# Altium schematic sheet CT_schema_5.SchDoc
size 479 x 328 mm
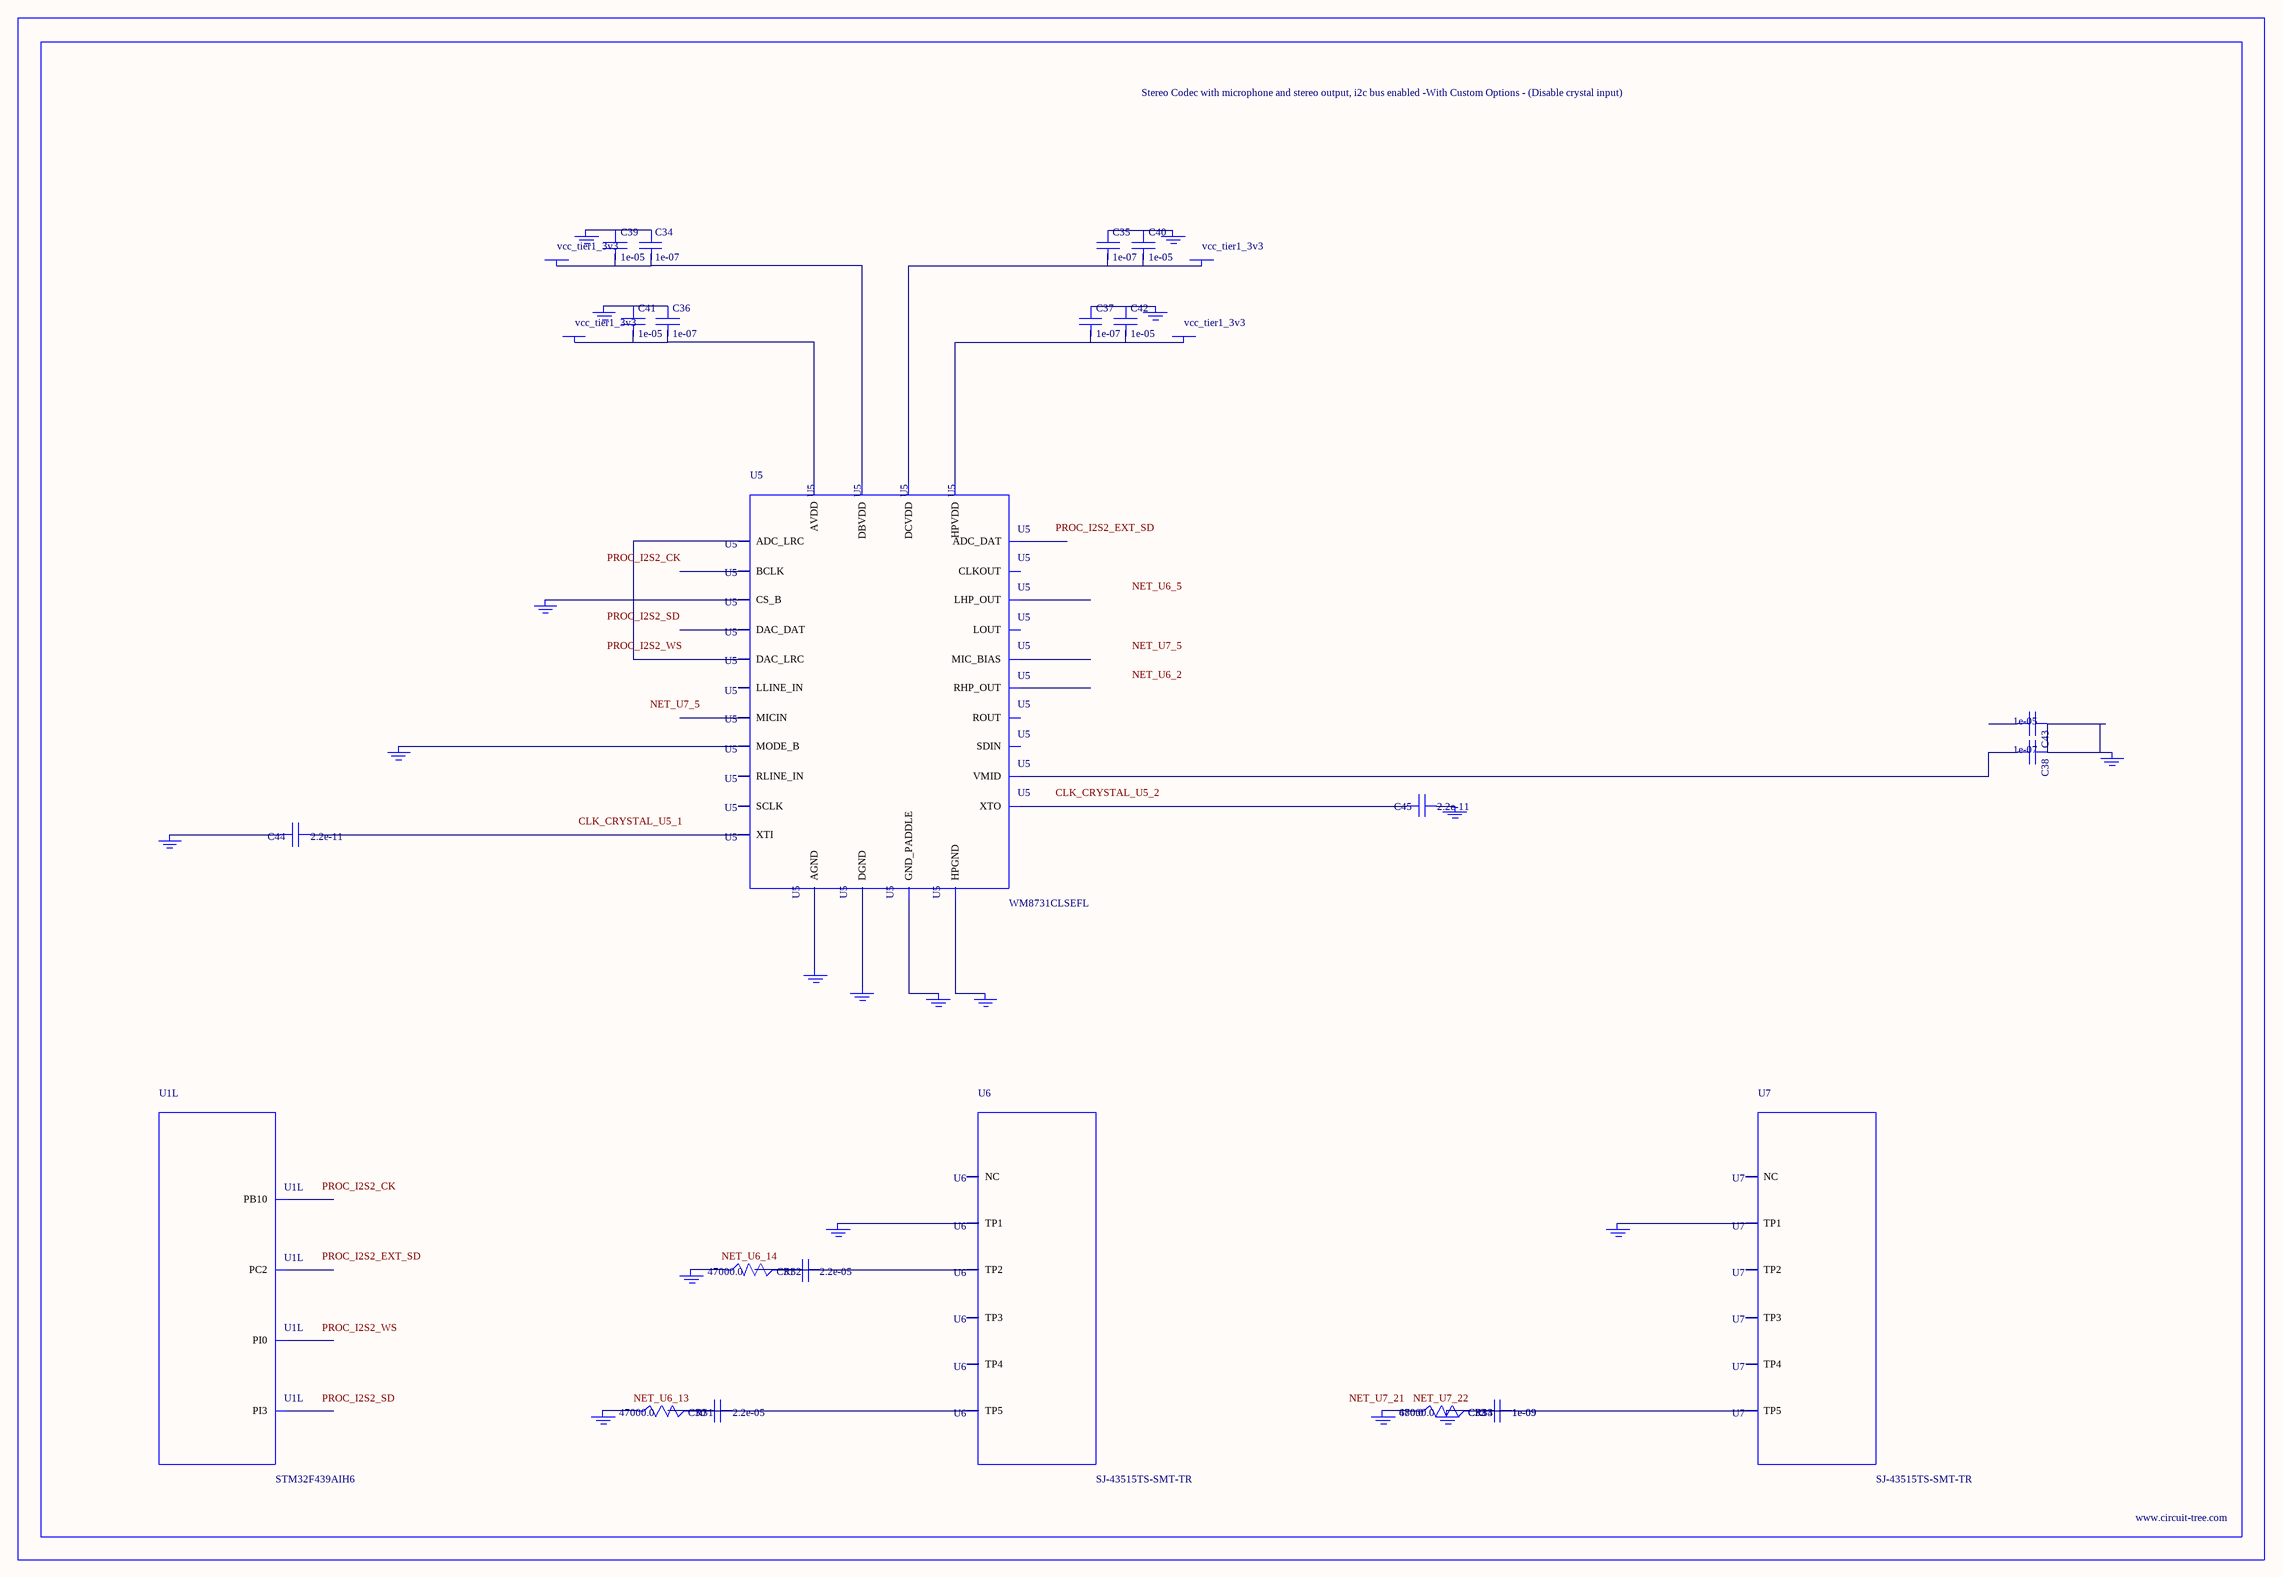
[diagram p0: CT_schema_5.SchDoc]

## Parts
BORDER4  (no value)
C30  2.2e-05  [C1210]
C31  2.2e-05  [C1210]
C32  1e-09  [C0402]
C33  1e-09  [C0402]
C34  1e-07  [C0402]
C35  1e-07  [C0402]
C36  1e-07  [C0402]
C37  1e-07  [C0402]
C38  1e-07  [C0402]
C39  1e-05  [C0805]
C40  1e-05  [C0805]
C41  1e-05  [C0805]
C42  1e-05  [C0805]
C43  1e-05  [C0805]
C44  2.2e-11  [C0402]
C45  2.2e-11  [C0402]
GND_INSTANCE_4_0  (no value)
GND_INSTANCE_4_1  (no value)
GND_INSTANCE_4_2  (no value)
GND_INSTANCE_4_3  (no value)
GND_INSTANCE_4_4  (no value)
GND_INSTANCE_4_5  (no value)
GND_INSTANCE_4_6  (no value)
GND_INSTANCE_4_7  (no value)
GND_INSTANCE_4_8  (no value)
GND_INSTANCE_4_9  (no value)
GND_INSTANCE_4_10  (no value)
GND_INSTANCE_4_11  (no value)
GND_INSTANCE_4_12  (no value)
GND_INSTANCE_4_13  (no value)
GND_INSTANCE_4_14  (no value)
GND_INSTANCE_4_15  (no value)
GND_INSTANCE_4_16  (no value)
GND_INSTANCE_4_17  (no value)
GND_INSTANCE_4_18  (no value)
POWER_INSTANCE_4_0  vcc_tier1_3v3
POWER_INSTANCE_4_1  vcc_tier1_3v3
POWER_INSTANCE_4_2  vcc_tier1_3v3
POWER_INSTANCE_4_3  vcc_tier1_3v3
R31  47000.0  [R0603]
R32  47000.0  [R0603]
R33  47000.0  [R0603]
R34  680.0  [R0603]
U1  STM32F439AIH6  [UFBGA169]  (part L of 12)
U5  WM8731CLSEFL  [QFN-28]
U6  SJ-43515TS-SMT-TR  [SJ-43515TS-SMT-TR]
U7  SJ-43515TS-SMT-TR  [SJ-43515TS-SMT-TR]

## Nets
NetC30_1: C30.1 C30.2 R31.2 U6.5(TP5)
NetC31_1: C31.1 C31.2 R32.2 U6.2(TP2)
NetC32_1: C32.1 C32.2 C33.1 C33.2 GND_INSTANCE_4_18.0(GND) R33.2 R34.2 U7.5(TP5)
NetC34_1: C34.1 C39.1 GND_INSTANCE_4_3.0(GND)
NetC34_2: C34.2 C39.2 POWER_INSTANCE_4_1.0(PWR) U5.5(DBVDD)
NetC35_1: C35.1 C40.1 GND_INSTANCE_4_2.0(GND)
NetC35_2: C35.2 C40.2 POWER_INSTANCE_4_0.0(PWR) U5.3(DCVDD)
NetC36_1: C36.1 C41.1 GND_INSTANCE_4_6.0(GND)
NetC36_2: C36.2 C41.2 POWER_INSTANCE_4_3.0(PWR) U5.18(AVDD)
NetC37_1: C37.1 C42.1 GND_INSTANCE_4_4.0(GND)
NetC37_2: C37.2 C42.2 POWER_INSTANCE_4_2.0(PWR) U5.12(HPVDD)
NetC38_1: C38.1 C43.1 GND_INSTANCE_4_7.0(GND)
NetC38_2: C38.2 U5.20(VMID)
NetC44_1: C44.1 U5.1(XTI)
NetC44_2: C44.2 GND_INSTANCE_4_0.0(GND)
NetC45_1: C45.1 GND_INSTANCE_4_1.0(GND)
NetC45_2: C45.2 U5.2(XTO)
NetGND_INSTANCE_4_5_0: GND_INSTANCE_4_5.0(GND) U5.15(HPGND)
NetGND_INSTANCE_4_8_0: GND_INSTANCE_4_8.0(GND) U5.25(MODE_B)
NetGND_INSTANCE_4_9_0: GND_INSTANCE_4_9.0(GND) U5.26(CS_B)
NetGND_INSTANCE_4_10_0: GND_INSTANCE_4_10.0(GND) U5.29(GND_PADDLE)
NetGND_INSTANCE_4_11_0: GND_INSTANCE_4_11.0(GND) U5.4(DGND)
NetGND_INSTANCE_4_12_0: GND_INSTANCE_4_12.0(GND) U5.19(AGND)
NetGND_INSTANCE_4_13_0: GND_INSTANCE_4_13.0(GND) U6.1(TP1)
NetGND_INSTANCE_4_14_0: GND_INSTANCE_4_14.0(GND) R32.1
NetGND_INSTANCE_4_15_0: GND_INSTANCE_4_15.0(GND) R31.1
NetGND_INSTANCE_4_16_0: GND_INSTANCE_4_16.0(GND) U7.1(TP1)
NetGND_INSTANCE_4_17_0: GND_INSTANCE_4_17.0(GND) R33.1 R34.1
NetU5_9: U5.9(DAC_LRC) U5.11(ADC_LRC)

Not connected (* = marked no-connect by the designer): C43 2; U1 A12(PI3) B13(PI0) H6(PC2) L9(PB10); U5 6(CLKOUT) 7(BCLK) 8(DAC_DAT) 10(ADC_DAT) 13(LHP_OUT) 14(RHP_OUT) 16(LOUT) 17(ROUT) 21(MIC_BIAS) 22(MICIN) 23(RLINE_IN) 24(LLINE_IN) 27(SDIN) 28(SCLK); U6 3(TP3) 4(TP4) 6(NC); U7 2(TP2) 3(TP3) 4(TP4) 6(NC)

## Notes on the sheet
- Labels drawn without touching a wire or pin: CLK_CRYSTAL_U5_1, CLK_CRYSTAL_U5_2, NET_U6_2, NET_U6_5, NET_U6_13, NET_U6_14, NET_U7_5, NET_U7_21, NET_U7_22, PROC_I2S2_CK, PROC_I2S2_EXT_SD, PROC_I2S2_SD, PROC_I2S2_WS

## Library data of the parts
BORDER4 = BORDER_PAGE4
C30 C31 = C1210C224K5RACTU
C32 C33 = C0402C102K3RAC
C34-C38 = C0402C104K3RACTU
C39-C43 = C0805C106K8RACTU
C44 C45 = C0402C220K3RAC
GND_INSTANCE_4_0-GND_INSTANCE_4_18 = GND
POWER_INSTANCE_4_0-POWER_INSTANCE_4_3 = PWR
R31-R33 = RC0603JR-0747KL
R34 = RC0603JR-07680RL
